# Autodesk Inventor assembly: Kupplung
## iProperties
Author: Administrator
Created: 2003-04
Part Number: Kupplung
Document SubType Name: Baugruppe
Designer: Administrator
Control State: 0
Master: False
Checked Out: False
PropertySet Name: Design Tracking Control
Shininess: 20.0
Angle Display Precision: 2
Document Length Units: 11269
Document Angle Units: 11283
Document Time Units: 11279
Document Mass Units: 11290
Document Length Units Precision: 3
Document Angle Units Precision: 2
Compacted: False
PropertySet Name: _Private Model Information
Density: 0.0
Volumn: 0.0
Area: 0.0
PropertySet Name: Model Information
